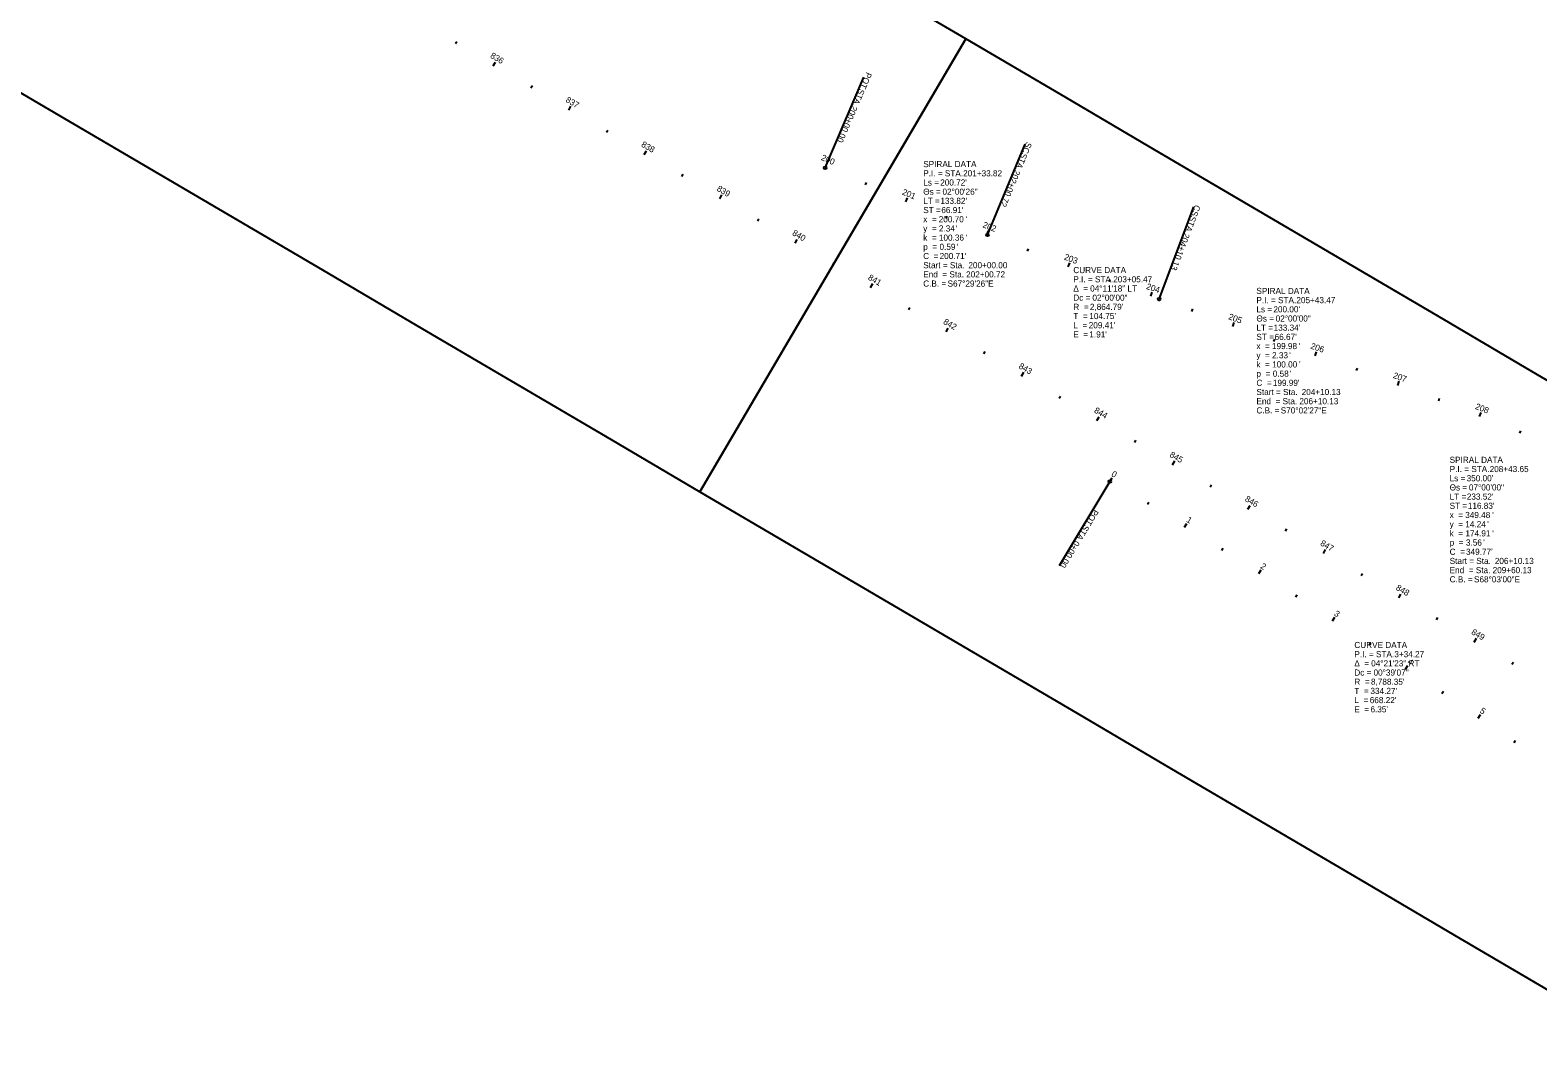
# Model space of a CAD drawing. Extents: x 75725 to 90554, y 518585 to 527848.
# Drawn here: x 85137 to 86859, y 522596 to 523756 of the extents above; entities that cross this region are included whole.
import ezdxf

# ---------------------------------------------------------------- set-up
doc = ezdxf.new("R2010")
doc.units = 0
for name, color, linetype in [('GE_P_Alignment_100_Cardinal_Points', 7, 'Continuous'), ('GE_P_Alignment_100_Curve_Data', 7, 'Continuous'), ('GE_P_Alignment_100_Stations', 7, 'Continuous'), ('SH_Named_Boundary', 7, 'Continuous')]:
    doc.layers.add(name, color=color, linetype=linetype)

msp = doc.modelspace()

# ---------------------------------------------------------------- linework, layer by layer
at = {"layer": 'GE_P_Alignment_100_Cardinal_Points'}
for p, q in [((86045, 523599.1), (86089.3, 523702.5)), ((86230.4, 523522.3), (86273.6, 523626.2)), ((86426.5, 523449.1), (86466.2, 523554.4)), ((86370.3, 523240.6), (86312.2, 523144.2))]:
    msp.add_line(p, q, dxfattribs=at)
for centre in [(86045, 523599.1), (86230.4, 523522.3), (86426.5, 523449.1), (86370.3, 523240.6)]:
    msp.add_circle(centre, 1.5, dxfattribs=at)
at = {"layer": 'GE_P_Alignment_100_Stations'}
for p, q in [((85622.6, 523741), (85624.1, 523743.5)), ((85665.7, 523715.6), (85668.3, 523719.9)), ((85708.8, 523690.3), (85710.4, 523692.9)), ((85751.9, 523665), (85754.5, 523669.3)), ((85795.1, 523639.7), (85796.6, 523642.2)), ((85838.2, 523614.3), (85840.7, 523618.6)), ((85881.3, 523589), (85882.8, 523591.6)), ((86045, 523599.1), (86046.9, 523603.7)), ((86091, 523579.5), (86092.1, 523582.2)), ((85924.4, 523563.7), (85926.9, 523568)), ((86137, 523560), (86138.9, 523564.7)), ((85967.5, 523538.4), (85969, 523540.9)), ((86183.2, 523541), (86184.4, 523543.8)), ((86229.7, 523522.6), (86231.5, 523527.2)), ((86010.6, 523513), (86013.1, 523517.3)), ((86276.1, 523503.8), (86277.2, 523506.6)), ((86053.7, 523487.7), (86055.2, 523490.3)), ((86322.7, 523485.8), (86324.5, 523490.5)), ((86369.7, 523468.6), (86370.7, 523471.5)), ((86096.8, 523462.4), (86099.4, 523466.7)), ((86416.9, 523452.3), (86418.5, 523457)), ((86140, 523437.1), (86141.5, 523439.6)), ((86463.9, 523435), (86464.9, 523437.9)), ((86183.1, 523411.7), (86185.6, 523416)), ((86510.7, 523417.6), (86512.4, 523422.3)), ((86557.7, 523400.5), (86558.7, 523403.4)), ((86226.2, 523386.4), (86227.7, 523389)), ((86604.9, 523384.1), (86606.5, 523388.8)), ((86269.3, 523361.1), (86271.8, 523365.4)), ((86652.1, 523367.4), (86653.1, 523370.2)), ((86699.1, 523350.4), (86700.8, 523355.1)), ((86312.4, 523335.8), (86313.9, 523338.3)), ((86746, 523333), (86747, 523335.8)), ((86355.5, 523310.4), (86358, 523314.7)), ((86792.6, 523314.9), (86794.4, 523319.6)), ((86838.8, 523296), (86840, 523298.7)), ((86398.6, 523285.1), (86400.1, 523287.7)), ((86441.7, 523259.8), (86444.3, 523264.1)), ((86370.3, 523240.6), (86372.9, 523244.8)), ((86484.8, 523234.5), (86486.4, 523237)), ((86413.1, 523214.6), (86414.6, 523217.2)), ((86528, 523209.1), (86530.5, 523213.4)), ((86455.7, 523188.5), (86458.3, 523192.7)), ((86571.1, 523183.8), (86572.6, 523186.4)), ((86498.1, 523162), (86499.7, 523164.6)), ((86614.2, 523158.5), (86616.7, 523162.8)), ((86540.4, 523135.4), (86543.1, 523139.6)), ((86657.3, 523133.1), (86658.8, 523135.7)), ((86582.6, 523108.5), (86584.2, 523111)), ((86700.4, 523107.8), (86702.9, 523112.1)), ((86624.6, 523081.4), (86627.3, 523085.5)), ((86743.5, 523082.5), (86745, 523085.1)), ((86666.4, 523054), (86668.1, 523056.5)), ((86786.6, 523057.2), (86789.2, 523061.5)), ((86708.1, 523026.4), (86710.9, 523030.5)), ((86829.7, 523031.8), (86831.3, 523034.4)), ((86749.6, 522998.5), (86751.3, 523001)), ((86791, 522970.4), (86793.8, 522974.6)), ((86832.2, 522942.1), (86833.9, 522944.6))]:
    msp.add_line(p, q, dxfattribs=at)
at = {"layer": 'SH_Named_Boundary'}
for points in [[(85127.9, 524379.5), (84824, 523862.2), (84931.8, 523798.8), (85039.6, 523735.5), (85147.4, 523672.2), (85255.1, 523608.9), (85362.9, 523545.6), (85470.7, 523482.3), (85578.5, 523419), (85686.2, 523355.6), (85794, 523292.3), (85901.8, 523229), (86205.7, 523746.4), (86097.9, 523809.7), (85990.2, 523873), (85882.4, 523936.3), (85774.6, 523999.6), (85666.8, 524062.9), (85559, 524126.2), (85451.3, 524189.6), (85343.5, 524252.9), (85235.7, 524316.2)], [(86205.7, 523746.4), (85901.8, 523229), (86009.6, 523165.7), (86117.4, 523102.4), (86225.1, 523039.1), (86332.9, 522975.8), (86440.7, 522912.4), (86548.5, 522849.1), (86656.3, 522785.8), (86764, 522722.5), (86871.8, 522659.2), (86979.6, 522595.9), (87283.5, 523113.2), (87175.7, 523176.5), (87068, 523239.8), (86960.2, 523303.2), (86852.4, 523366.5), (86744.6, 523429.8), (86636.8, 523493.1), (86529.1, 523556.4), (86421.3, 523619.7), (86313.5, 523683)]]:
    msp.add_lwpolyline(points, close=True, dxfattribs=at)

# ---------------------------------------------------------------- texts
at = {"layer": 'GE_P_Alignment_100_Cardinal_Points'}
for s, rotation, p in [('POT', 246.8214, (86092.1, 523708.9)), (' STA. ', 246.8214, (86085, 523692.4)), ('200+00.00', 246.8214, (86075.7, 523670.7)), ('SC', 247.4355, (86274.9, 523629.1)), (' STA. ', 247.4355, (86270.8, 523619.2)), ('202+00.72', 247.4355, (86261.7, 523597.3)), ('CS', 249.3741, (86467.4, 523557.3)), (' STA. ', 249.3741, (86463.6, 523547.2)), ('204+10.13', 249.3741, (86455.3, 523525.1)), ('POT', 238.9262, (86351.8, 523209.6)), (' STA. ', 238.9262, (86342.5, 523194.2)), ('0+00.00', 238.9262, (86330.3, 523173.9))]:
    msp.add_text(s, height=7, rotation=rotation, dxfattribs=at).set_placement(p)
at = {"layer": 'GE_P_Alignment_100_Curve_Data'}
for s, p in [('SPIRAL DATA', (86157, 523599.8)), ('P.I. = STA. ', (86157, 523589.3)), ('201+33.82', (86202.6, 523589.3)), ('Θs = ', (86157, 523568.3)), ('Ls = ', (86157, 523578.8)), ("200.72'", (86176.4, 523578.8)), ('02°00\'26"', (86179, 523568.3)), ('ST = ', (86157, 523547.3)), ('LT = ', (86157, 523557.8)), ("133.82'", (86176.6, 523557.8)), ("66.91'", (86177.7, 523547.3)), ('x  = ', (86157, 523536.8)), ('200.70', (86174.7, 523536.8)), ("'", (86205.4, 523536.8)), ('y  = ', (86157, 523526.3)), ('k  = ', (86157, 523515.8)), ('2.34', (86174.9, 523526.3)), ('100.36', (86174.9, 523515.8)), ("'", (86194.4, 523526.3)), ("'", (86205.7, 523515.8)), ('p  = ', (86157, 523505.3)), ('0.59', (86175.6, 523505.3)), ("'", (86195.2, 523505.3)), ('C  = ', (86157, 523494.8)), ('Start = Sta. ', (86157, 523484.3)), ("200.71'", (86175.7, 523494.8)), ('200+00.00', (86208.6, 523484.3)), ('CURVE DATA', (86328.5, 523478.7)), ('C.B. = ', (86157, 523463.3)), ('End  = Sta. ', (86157, 523473.8)), ('S67°29\'26"E', (86184.8, 523463.3)), ('202+00.72', (86206, 523473.8)), ('P.I. = STA. ', (86328.5, 523468.2)), ('203+05.47', (86374.1, 523468.2)), ('Δ  = ', (86328.5, 523457.7)), ('Dc = ', (86328.5, 523447.2)), ('04°11\'18" LT', (86347.7, 523457.7)), ('02°00\'00"', (86350.3, 523447.2)), ('SPIRAL DATA', (86537.7, 523454.9)), ('P.I. = STA. ', (86537.7, 523444.4)), ('205+43.47', (86583.4, 523444.4)), ('R  = ', (86328.5, 523436.7)), ("104.75'", (86346.8, 523426.2)), ("2,864.79'", (86347.4, 523436.7)), ('Ls = ', (86537.7, 523433.9)), ("200.00'", (86557.1, 523433.9)), ('T  = ', (86328.5, 523426.2)), ('L  = ', (86328.5, 523415.7)), ("209.41'", (86346.1, 523415.7)), ('Θs = ', (86537.7, 523423.4)), ('LT = ', (86537.7, 523412.9)), ("133.34'", (86557.4, 523412.9)), ('02°00\'00"', (86559.7, 523423.4)), ('E  = ', (86328.5, 523405.2)), ("1.91'", (86346.8, 523405.2)), ('ST = ', (86537.7, 523402.4)), ('199.98', (86555.5, 523391.9)), ("66.67'", (86558.5, 523402.4)), ("'", (86586.2, 523391.9)), ('x  = ', (86537.7, 523391.9)), ('y  = ', (86537.7, 523381.4)), ('2.33', (86555.6, 523381.4)), ("'", (86575.2, 523381.4)), ('p  = ', (86537.7, 523360.4)), ('k  = ', (86537.7, 523370.9)), ('100.00', (86555.7, 523370.9)), ('0.58', (86556.4, 523360.4)), ("'", (86575.9, 523360.4)), ("'", (86586.4, 523370.9)), ('C  = ', (86537.7, 523349.9)), ("199.99'", (86556.5, 523349.9)), ('Start = Sta. ', (86537.7, 523339.4)), ('End  = Sta. ', (86537.7, 523328.9)), ('206+10.13', (86586.8, 523328.9)), ('204+10.13', (86589.4, 523339.4)), ('C.B. = ', (86537.7, 523318.4)), ('S70°02\'27"E', (86565.5, 523318.4)), ('SPIRAL DATA', (86758.5, 523261.9)), ('P.I. = STA. ', (86758.5, 523251.4)), ('Ls = ', (86758.5, 523240.9)), ("350.00'", (86777.9, 523240.9)), ('208+43.65', (86804.2, 523251.4)), ('Θs = ', (86758.5, 523230.4)), ('LT = ', (86758.5, 523219.9)), ("233.52'", (86778.1, 523219.9)), ('07°00\'00"', (86780.5, 523230.4)), ('ST = ', (86758.5, 523209.4)), ("116.83'", (86779.3, 523209.4)), ('y  = ', (86758.5, 523188.4)), ('x  = ', (86758.5, 523198.9)), ('349.48', (86776.3, 523198.9)), ('14.24', (86776.4, 523188.4)), ("'", (86801.5, 523188.4)), ("'", (86807, 523198.9)), ('k  = ', (86758.5, 523177.9)), ('174.91', (86776.5, 523177.9)), ("'", (86807.2, 523177.9)), ('C  = ', (86758.5, 523156.9)), ('p  = ', (86758.5, 523167.4)), ('3.56', (86777.1, 523167.4)), ("349.77'", (86777.2, 523156.9)), ("'", (86796.7, 523167.4)), ('Start = Sta. ', (86758.5, 523146.4)), ('End  = Sta. ', (86758.5, 523135.9)), ('209+60.13', (86807.6, 523135.9)), ('206+10.13', (86810.1, 523146.4)), ('C.B. = ', (86758.5, 523125.4)), ('S68°03\'00"E', (86786.3, 523125.4)), ('CURVE DATA', (86649.6, 523050.4)), ('P.I. = STA. ', (86649.6, 523039.9)), ('3+34.27', (86695.3, 523039.9)), ('Δ  = ', (86649.6, 523029.4)), ('Dc = ', (86649.6, 523018.9)), ('04°21\'23" RT', (86668.8, 523029.4)), ('00°39\'07"', (86671.5, 523018.9)), ('T  = ', (86649.6, 522997.9)), ('R  = ', (86649.6, 523008.4)), ("334.27'", (86668, 522997.9)), ("8,788.35'", (86668.6, 523008.4)), ('L  = ', (86649.6, 522987.4)), ("668.22'", (86667.2, 522987.4)), ('E  = ', (86649.6, 522976.9)), ("6.35'", (86668, 522976.9))]:
    msp.add_text(s, height=7, dxfattribs=at).set_placement(p)
at = {"layer": 'GE_P_Alignment_100_Stations'}
for s, rotation, p in [('836', 329.5684, (85661.6, 523725.3)), ('837', 329.5684, (85747.7, 523674.7)), ('838', 329.5684, (85834.1, 523623.9)), ('200', 336.8214, (86039.7, 523608.2)), ('839', 329.5684, (85920.4, 523573.3)), ('201', 337.3196, (86132.2, 523568.8)), ('202', 338.8142, (86224.3, 523531.3)), ('840', 329.5684, (86006.6, 523522.7)), ('203', 339.4211, (86317.3, 523494.5)), ('841', 329.5684, (86093.2, 523471.8)), ('204', 341.4211, (86411.2, 523460.8)), ('842', 329.5684, (86179.2, 523421.3)), ('205', 339.7779, (86505.1, 523426.3)), ('206', 341.1766, (86599, 523392.7)), ('843', 329.5684, (86265.4, 523370.6)), ('207', 339.9216, (86693.2, 523359.2)), ('844', 329.5684, (86351.6, 523320)), ('208', 338.3231, (86787.1, 523323.8)), ('845', 329.5684, (86437.8, 523269.4)), ('0', 328.9262, (86371.2, 523247.3)), ('846', 329.5684, (86523.9, 523218.8)), ('1', 328.2743, (86457, 523195)), ('847', 329.5684, (86610, 523168.2)), ('2', 327.6223, (86541.6, 523142.1)), ('848', 329.5684, (86696.4, 523117.4)), ('3', 326.9703, (86625.8, 523088)), ('849', 329.5684, (86782.6, 523066.8)), ('4', 326.3184, (86709.4, 523033)), ('5', 325.6664, (86792.3, 522977.1))]:
    msp.add_text(s, height=7, rotation=rotation, dxfattribs=at).set_placement(p)

doc.saveas('drawing.dxf')
